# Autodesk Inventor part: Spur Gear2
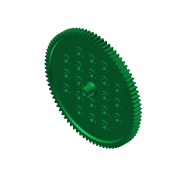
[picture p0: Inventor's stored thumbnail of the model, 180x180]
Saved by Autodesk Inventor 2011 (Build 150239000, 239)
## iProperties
Created: 2010-04
Part Number: Spur Gear2
Material: ABS Plastic
Document SubType Name: Modeling
Designer: Phil
Categories: <?xml version="1.0" encoding="UTF-16"?> <MemberInstance><Categories><FamilyTemplate><FamilyTemplateParameter ValueType="xs:double" Id="1" ObjectReferenceKey="da
Mass: 20.4005 g
Surface Area: 204.791 cm^2
Volume: 19.2457 cm^3
Density: 1.06 g/cm^3
CustomPartVersion: 1
Author: Phil
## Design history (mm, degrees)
sketch "Sketch1"
  geometry: C1 r 45.297 at (0, 0)
  constraints: 1 centre point
  dimensions: "d0" = 90.59333 diameter of C1 (= da_da)
extrude "Extrusion1" new body sketch "Sketch1" distance "d1" = 6.35 (= da_b); taper "d2" = 0 deg
sketch "Sketch2"
  geometry: C1 r 45.297 at (0, 0) reference; C2 r 44.45 at (0, 0)
  constraints: 1 centre point, 1 coincident
  dimensions: "d3" = 88.9 diameter of C2 (= da_dw)
feature "Pitch Diameter" sketch "Sketch2" dims "d4" = 76.2, "d5" = 0
workplane "Work Plane1"
workplane "Work Plane2"
workplane "Work Plane3"
feature "Spur Gear" dims "da_b" = 6.35, "da_d" = 88.9, "da_aw" = 50.8, "da_da" = 90.59333, "da_df" = 85.83083, "da_dw" = 88.9, angle "da_beta" = 0 deg, "da_lefttooth" = 0, "da_righttooth" = 0
sketch "Sketch3"
  geometry: C1 r 40.996 at (0, 0); A1 r 45.297 centre (0, 0) between (-2.963, 45.2) and (-3.807, 45.136) reference
  constraints: 1 centre point, 1 coincident
  dimensions: "d20" = 81.9912 diameter of C1
extrude "Extrusion2" cut sketch "Sketch3" distance "d21" = 1.9304; taper "d22" = -10 deg
workplane "Work Plane4"
fillet "Fillet1" dims "d23" = 0.9906
mirror "Mirror1"
sketch "Sketch4"
  geometry: C1 r 39.824 at (0, 0) reference; C2 r 4.178 at (0, -25.4)
  constraints: 1 centre point, 1 vertical alignment
  dimensions: "d24" = 8.3566 diameter of C2; "d25" = 25.4 distance of C2.centre C1.centre
extrude "Extrusion3" join sketch "Sketch4" distance "d26" = 0.9144; taper "d27" = 0 deg
sketch "Sketch5"
  geometry: C1 r 39.824 at (0, 0) reference; C2 r 5.88 at (-4.125, -25.4)
  constraints: 1 centre point
  dimensions: "d28" = 11.7602 diameter of C2; "d29" = 25.4 vertical distance of C1.centre C2.centre
extrude "Extrusion4" join sketch "Sketch5" distance "d30" = 1.9304; taper "d31" = 0 deg
sketch "Sketch6"
  geometry: C1 r 5.88 at (0, 0) reference; C2 r 4.674 at (0, 0); 1 further point
  constraints: 1 centre point, 1 coincident
  dimensions: "d32" = 9.3472 diameter of C2
extrude "Extrusion5" cut sketch "Sketch6" distance "d33" = 2.9972; taper "d34" = 0 deg
sketch "Sketch7"
  geometry: C1 r 4.178 at (0, 0) reference; 1 further point
hole "Hole1" sketch "Sketch7" at (0, 0) diameter "d35" = 4.3434; stored, may be unused: countersink angle "d39" = 82 deg, drill point angle "d41" = 118 deg; dims "d36" = 19.05, "d37" = 9.525, "d38" = 6.35, "d40" = 25.4
sketch "Sketch8"
  geometry: C1 r 39.824 at (0, 0) reference; C2 r 4.001 at (0, 0)
  constraints: 1 centre point, 1 coincident
  dimensions: "d48" = 8.001 diameter of C2
extrude "Extrusion6" join sketch "Sketch8" distance "d49" = 8.2804; taper "d50" = 0 deg
sketch "Sketch9"
  geometry: C1 r 39.824 at (0, 0) reference; C2 r 4.001 at (0, 0)
  constraints: 1 centre point, 1 coincident
  dimensions: "d51" = 8.001 diameter of C2
extrude "Extrusion7" join sketch "Sketch9" distance "d52" = 1.9304; taper "d53" = 0 deg
chamfer "Chamfer1" distance "d54" = 1.524; stored, may be unused: second distance "d55" = 3.175, angle "d56" = 45 deg
sketch "Sketch10"
  geometry: L1 (1.612, 0.952)-(1.558, 1.007); L2 (1.558, 1.025)-(1.612, 1.079); L3 (1.612, 1.104)-(1.612, 1.079); L4 (1.558, 1.177)-(1.612, 1.231); L5 (1.612, 1.362)-(1.612, 1.231); L6 (1.232, 1.612)-(1.177, 1.558); L7 (1.159, 1.558)-(1.105, 1.612); L8 (1.079, 1.612)-(1.105, 1.612); L9 (1.232, 1.612)-(1.362, 1.612); L10 (1.612, 0.952)-(1.612, -0.952); L11 (1.558, -1.007)-(1.612, -0.952); L12 (1.612, 1.104)-(1.558, 1.159); L13 (1.079, 1.612)-(1.025, 1.558); L14 (-1.362, 1.612)-(-1.231, 1.612); L15 (-1.177, 1.558)-(-1.231, 1.612); L16 (1.007, 1.558)-(0.952, 1.612); L17 (-0.952, 1.613)-(0.952, 1.612); L18 (-0.952, 1.613)-(-1.007, 1.558); L19 (-1.024, 1.558)-(-1.079, 1.612); L20 (-1.104, 1.613)-(-1.079, 1.612); L21 (-1.104, 1.613)-(-1.159, 1.558); L22 (1.613, -1.079)-(1.558, -1.024); L23 (1.613, -1.079)-(1.612, -1.105); L24 (1.558, -1.159)-(1.612, -1.105); L25 (1.613, -1.231)-(1.558, -1.177); L26 (1.613, -1.231)-(1.612, -1.362); L27 (1.362, -1.612)-(1.231, -1.612); L28 (1.177, -1.558)-(1.231, -1.612); L29 (1.104, -1.613)-(1.079, -1.612); L30 (1.024, -1.558)-(1.079, -1.612); L31 (0.952, -1.613)-(1.007, -1.558); L32 (0.952, -1.613)-(-0.952, -1.612); L33 (1.104, -1.613)-(1.159, -1.558); L34 (-1.007, -1.558)-(-0.952, -1.612); L35 (-1.079, -1.612)-(-1.025, -1.558); L36 (-1.079, -1.612)-(-1.105, -1.612); L37 (-1.159, -1.558)-(-1.105, -1.612); L38 (-1.232, -1.612)-(-1.177, -1.558); L39 (-1.612, -0.952)-(-1.558, -1.007); L40 (-1.558, -1.025)-(-1.612, -1.079); L41 (-1.612, -1.104)-(-1.612, -1.079); L42 (-1.612, -1.104)-(-1.558, -1.159); L43 (-1.558, -1.177)-(-1.612, -1.231); L44 (-1.612, -1.362)-(-1.612, -1.231); L45 (-1.232, -1.612)-(-1.362, -1.612); L46 (-1.612, -0.952)-(-1.612, 0.952); L47 (-1.558, 1.007)-(-1.612, 0.952); L48 (-1.613, 1.079)-(-1.558, 1.024); L49 (-1.613, 1.079)-(-1.612, 1.105); L50 (-1.558, 1.159)-(-1.612, 1.105); L51 (-1.613, 1.231)-(-1.558, 1.177); L52 (-1.613, 1.231)-(-1.612, 1.362); A1 r 0.013 centre (1.567, 1.016) between (1.558, 1.025) and (1.558, 1.007); A2 r 0.013 centre (1.567, 1.168) between (1.558, 1.177) and (1.558, 1.159); A3 r 0.25 centre (1.362, 1.362) between (1.612, 1.362) and (1.362, 1.612); A4 r 0.013 centre (1.168, 1.567) between (1.159, 1.558) and (1.177, 1.558); A5 r 0.012 centre (-1.016, 1.566) between (-1.024, 1.558) and (-1.007, 1.558); A6 r 0.012 centre (-1.168, 1.566) between (-1.177, 1.558) and (-1.159, 1.558); A7 r 0.013 centre (1.016, 1.567) between (1.007, 1.558) and (1.025, 1.558); A8 r 0.012 centre (1.566, -1.016) between (1.558, -1.007) and (1.558, -1.024); A9 r 0.013 centre (1.567, -1.168) between (1.558, -1.159) and (1.558, -1.177); A10 r 0.25 centre (1.362, -1.362) between (1.362, -1.612) and (1.612, -1.362); A11 r 0.012 centre (1.168, -1.566) between (1.177, -1.558) and (1.159, -1.558); A12 r 0.012 centre (1.016, -1.566) between (1.024, -1.558) and (1.007, -1.558); A13 r 0.013 centre (-1.016, -1.567) between (-1.007, -1.558) and (-1.025, -1.558); A14 r 0.013 centre (-1.168, -1.567) between (-1.159, -1.558) and (-1.177, -1.558); A15 r 0.013 centre (-1.567, -1.168) between (-1.558, -1.177) and (-1.558, -1.159); A16 r 0.013 centre (-1.567, -1.016) between (-1.558, -1.025) and (-1.558, -1.007); A17 r 0.25 centre (-1.362, -1.362) between (-1.612, -1.362) and (-1.362, -1.612); A18 r 0.25 centre (-1.362, 1.362) between (-1.362, 1.612) and (-1.612, 1.362); A19 r 0.013 centre (-1.567, 1.168) between (-1.558, 1.159) and (-1.558, 1.177); A20 r 0.012 centre (-1.566, 1.016) between (-1.558, 1.007) and (-1.558, 1.024); 1 further point
  constraints: 104 end point, 40 point on circle, 20 centre point
feature "iFeature2:1" sketch "Sketch10"
body "Solid1"
pattern_linear "Rectangular Pattern1" dims "d44" = 12.7, "d47" = 12.7
body "Srf1"
other parameters: "d6" = 0, "d7" = 0.374 (computed from da_z), "d9" = 0, "d14" = 0, "d15" = 50.8 (= da_aw), "d16" = 0, "d17" = 0, "d18" = 0, "d19" = 50.8 (= da_aw)
